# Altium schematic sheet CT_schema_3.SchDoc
size 289 x 230 mm
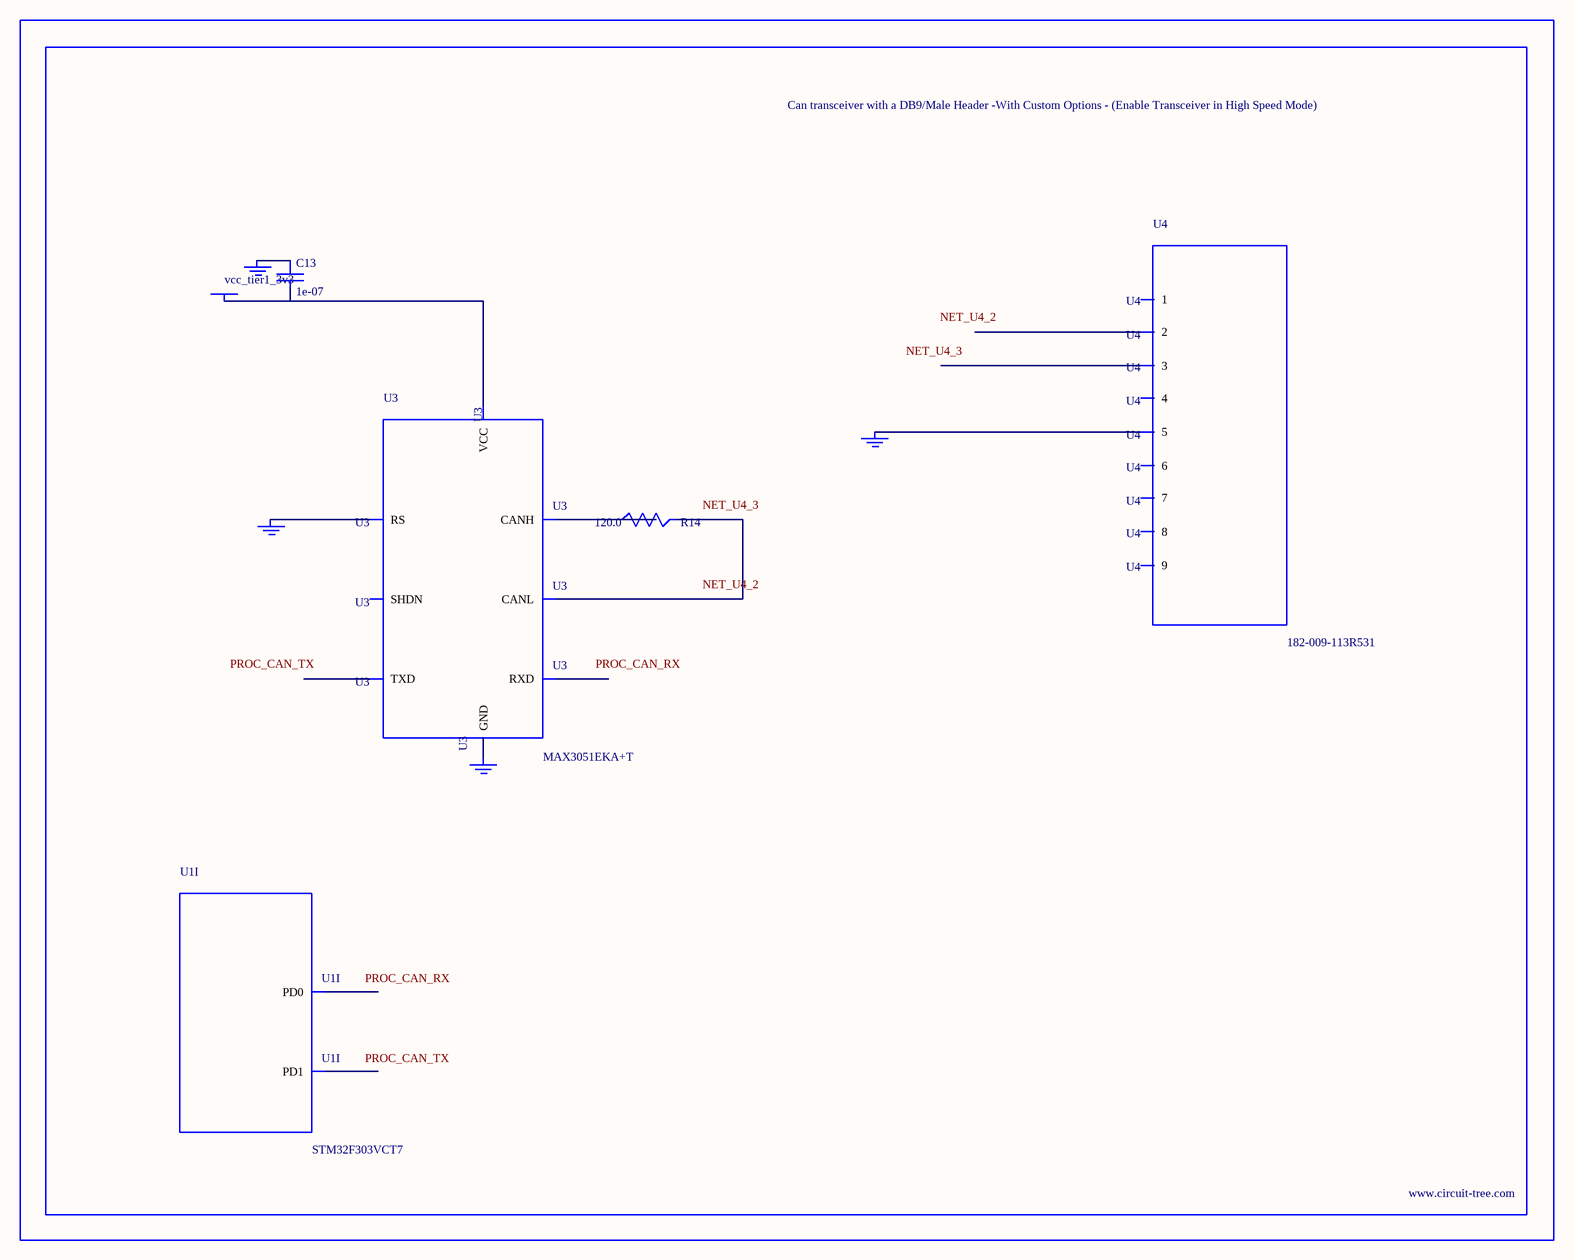
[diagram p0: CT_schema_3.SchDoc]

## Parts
BORDER2  (no value)
C13  1e-07  [C0402]
GND_INSTANCE_2_0  (no value)
GND_INSTANCE_2_1  (no value)
GND_INSTANCE_2_2  (no value)
GND_INSTANCE_2_3  (no value)
POWER_INSTANCE_2_0  vcc_tier1_3v3
R14  120.0  [R0603]
U1  STM32F303VCT7  [LQFP100]  (part I of 11)
U3  MAX3051EKA+T  [SOT-23-8]
U4  182-009-113R531  [182-009-MALE]

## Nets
NetC13_1: C13.1 GND_INSTANCE_2_0.0(GND)
NetC13_2: C13.2 POWER_INSTANCE_2_0.0(PWR) U3.3(VCC)
NetGND_INSTANCE_2_1_0: GND_INSTANCE_2_1.0(GND) U3.8(RS)
NetGND_INSTANCE_2_2_0: GND_INSTANCE_2_2.0(GND) U3.2(GND)
NetGND_INSTANCE_2_3_0: GND_INSTANCE_2_3.0(GND) U4.5
NetR14_1: R14.1 U3.7(CANH)
NetR14_2: R14.2 U3.6(CANL)

Not connected (* = marked no-connect by the designer): U1 81(PD0) 82(PD1); U3 1(TXD) 4(RXD) 5(SHDN); U4 1 2 3 4 6 7 8 9

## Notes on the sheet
- Labels drawn without touching a wire or pin: NET_U4_2, NET_U4_3, PROC_CAN_RX, PROC_CAN_TX

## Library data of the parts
BORDER2 = BORDER_PAGE2
C13 = C0402C104K3RACTU
GND_INSTANCE_2_0-GND_INSTANCE_2_3 = GND
POWER_INSTANCE_2_0 = PWR
R14 = RC0603JR-07120RL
